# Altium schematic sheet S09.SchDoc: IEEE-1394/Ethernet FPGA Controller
size 381 x 254 mm; Revision: 3.2; SheetNumber: 9; SheetTotal: 10
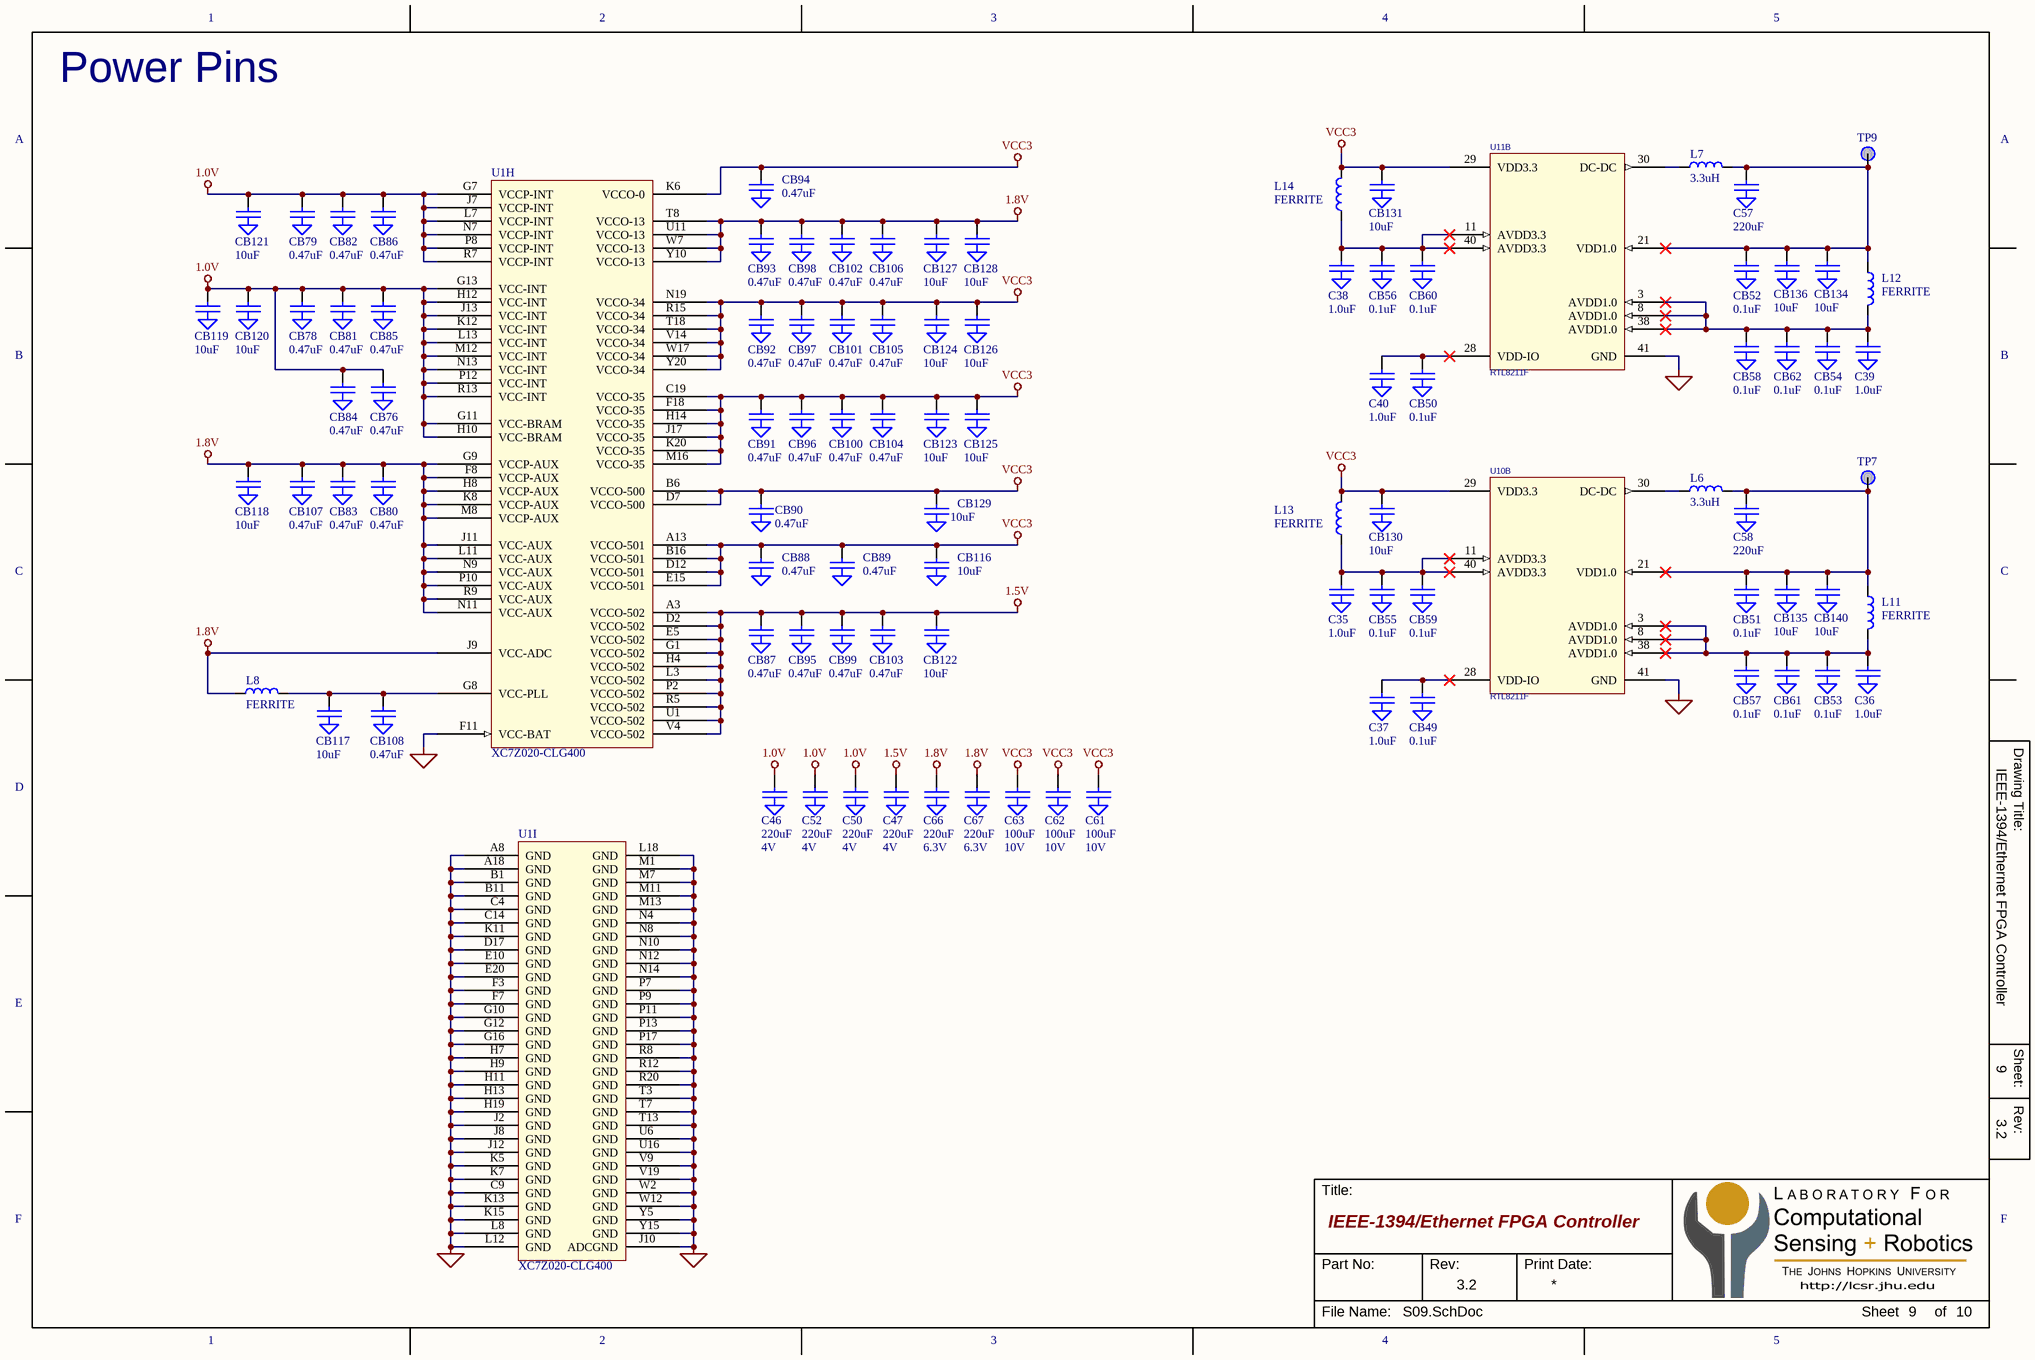
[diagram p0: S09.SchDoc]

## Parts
C35  1.0uF  [C0402]
C36  1.0uF  [C0402]
C37  1.0uF  [C0402]
C38  1.0uF  [C0402]
C39  1.0uF  [C0402]
C40  1.0uF  [C0402]
C46  220uF  Parameter 1: 4V  [C1206]
C47  220uF  Parameter 1: 4V  [C1206]
C50  220uF  Parameter 1: 4V  [C1206]
C52  220uF  Parameter 1: 4V  [C1206]
C57  220uF  [C1206]
C58  220uF  [C1206]
C61  100uF  Parameter 1: 10V  [C1210]
C62  100uF  Parameter 1: 10V  [C1210]
C63  100uF  Parameter 1: 10V  [C1210]
C66  220uF  Parameter 1: 6.3V  [C1210]
C67  220uF  Parameter 1: 6.3V  [C1210]
CB49  0.1uF  [C0201]
CB50  0.1uF  [C0201]
CB51  0.1uF  [C0201]
CB52  0.1uF  [C0201]
CB53  0.1uF  [C0201]
CB54  0.1uF  [C0201]
CB55  0.1uF  [C0201]
CB56  0.1uF  [C0201]
CB57  0.1uF  [C0201]
CB58  0.1uF  [C0201]
CB59  0.1uF  [C0201]
CB60  0.1uF  [C0201]
CB61  0.1uF  [C0201]
CB62  0.1uF  [C0201]
CB76  0.47uF  [CB0402]
CB78  0.47uF  [CB0402]
CB79  0.47uF  [CB0402]
CB80  0.47uF  [CB0402]
CB81  0.47uF  [CB0402]
CB82  0.47uF  [CB0402]
CB83  0.47uF  [CB0402]
CB84  0.47uF  [CB0402]
CB85  0.47uF  [CB0402]
CB86  0.47uF  [CB0402]
CB87  0.47uF  [CB0402]
CB88  0.47uF  [CB0402]
CB89  0.47uF  [CB0402]
CB90  0.47uF  [CB0402]
CB91  0.47uF  [CB0402]
CB92  0.47uF  [CB0402]
CB93  0.47uF  [CB0402]
CB94  0.47uF  [CB0402]
CB95  0.47uF  [CB0402]
CB96  0.47uF  [CB0402]
CB97  0.47uF  [CB0402]
CB98  0.47uF  [CB0402]
CB99  0.47uF  [CB0402]
CB100  0.47uF  [CB0402]
CB101  0.47uF  [CB0402]
CB102  0.47uF  [CB0402]
CB103  0.47uF  [CB0402]
CB104  0.47uF  [CB0402]
CB105  0.47uF  [CB0402]
CB106  0.47uF  [CB0402]
CB107  0.47uF  [CB0402]
CB108  0.47uF  [CB0402]
CB116  10uF  [CB0603]
CB117  10uF  [CB0603]
CB118  10uF  [CB0603]
CB119  10uF  [CB0603]
CB120  10uF  [CB0603]
CB121  10uF  [CB0603]
CB122  10uF  [CB0603]
CB123  10uF  [CB0603]
CB124  10uF  [CB0603]
CB125  10uF  [CB0603]
CB126  10uF  [CB0603]
CB127  10uF  [CB0603]
CB128  10uF  [CB0603]
CB129  10uF  [CB0603]
CB130  10uF  [CB0603]
CB131  10uF  [CB0603]
CB134  10uF  [CB0603]
CB135  10uF  [CB0603]
CB136  10uF  [CB0603]
CB140  10uF  [CB0603]
L6  3.3uH  [INDUCTOR-EPL2014]
L7  3.3uH  [INDUCTOR-EPL2014]
L8  FERRITE  [L0603]
L11  FERRITE  [l0402]
L12  FERRITE  [l0402]
L13  FERRITE  [l0402]
L14  FERRITE  [l0402]
TP7  PAD  [PAD25-SM]  (value not drawn)  (no BOM)
TP9  PAD  [PAD25-SM]  (value not drawn)  (no BOM)
U1  XC7Z020-CLG400  [BGA-400-08mm]  (parts H,I of 9)
U10  RTL8211F  [QFN-40-5MM]  (part B of 2)
U11  RTL8211F  [QFN-40-5MM]  (part B of 2)

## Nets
1.0V: C46.1 C50.1 C52.1 CB76.1 CB78.1 CB79.1 CB81.1 CB82.1 CB84.1 CB85.1 CB86.1 CB119.1 CB120.1 CB121.1 U1.G7(VCCP-INT) U1.G11(VCC-BRAM) U1.G13(VCC-INT) U1.H10(VCC-BRAM) U1.H12(VCC-INT) U1.J7(VCCP-INT) U1.J13(VCC-INT) U1.K12(VCC-INT) U1.L7(VCCP-INT) U1.L13(VCC-INT) U1.M12(VCC-INT) U1.N7(VCCP-INT) U1.N13(VCC-INT) U1.P8(VCCP-INT) U1.P12(VCC-INT) U1.R7(VCCP-INT) U1.R13(VCC-INT)
1.5V: C47.1 CB87.1 CB95.1 CB99.1 CB103.1 CB122.1 U1.A3(VCCO-502) U1.D2(VCCO-502) U1.E5(VCCO-502) U1.G1(VCCO-502) U1.H4(VCCO-502) U1.L3(VCCO-502) U1.P2(VCCO-502) U1.R5(VCCO-502) U1.U1(VCCO-502) U1.V4(VCCO-502)
1.8V: C66.1 C67.1 CB80.1 CB83.1 CB93.1 CB98.1 CB102.1 CB106.1 CB107.1 CB118.1 CB127.1 CB128.1 L8.1 U1.F8(VCCP-AUX) U1.G9(VCCP-AUX) U1.H8(VCCP-AUX) U1.J9(VCC-ADC) U1.J11(VCC-AUX) U1.K8(VCCP-AUX) U1.L11(VCC-AUX) U1.M8(VCCP-AUX) U1.N9(VCC-AUX) U1.N11(VCC-AUX) U1.P10(VCC-AUX) U1.R9(VCC-AUX) U1.T8(VCCO-13) U1.U11(VCCO-13) U1.W7(VCCO-13) U1.Y10(VCCO-13)
GND: C35.2(GND) C36.2(GND) C37.2(GND) C38.2(GND) C39.2(GND) C40.2(GND) C46.2(GND) C47.2(GND) C50.2(GND) C52.2(GND) C57.2(GND) C58.2(GND) C61.2(GND) C62.2(GND) C63.2(GND) C66.2(GND) C67.2(GND) CB49.2(GND) CB50.2(GND) CB51.2(GND) CB52.2(GND) CB53.2(GND) CB54.2(GND) CB55.2(GND) CB56.2(GND) CB57.2(GND) CB58.2(GND) CB59.2(GND) CB60.2(GND) CB61.2(GND) CB62.2(GND) CB76.2(GND) CB78.2(GND) CB79.2(GND) CB80.2(GND) CB81.2(GND) CB82.2(GND) CB83.2(GND) CB84.2(GND) CB85.2(GND) CB86.2(GND) CB87.2(GND) CB88.2(GND) CB89.2(GND) CB90.2(GND) CB91.2(GND) CB92.2(GND) CB93.2(GND) CB94.2(GND) CB95.2(GND) CB96.2(GND) CB97.2(GND) CB98.2(GND) CB99.2(GND) CB100.2(GND) CB101.2(GND) CB102.2(GND) CB103.2(GND) CB104.2(GND) CB105.2(GND) CB106.2(GND) CB107.2(GND) CB108.2(GND) CB116.2(GND) CB117.2(GND) CB118.2(GND) CB119.2(GND) CB120.2(GND) CB121.2(GND) CB122.2(GND) CB123.2(GND) CB124.2(GND) CB125.2(GND) CB126.2(GND) CB127.2(GND) CB128.2(GND) CB129.2(GND) CB130.2(GND) CB131.2(GND) CB134.2(GND) CB135.2(GND) CB136.2(GND) CB140.2(GND) U1.A8(GND) U1.A18(GND) U1.B1(GND) U1.B11(GND) U1.C4(GND) U1.C9(GND) U1.C14(GND) U1.D17(GND) U1.E10(GND) U1.E20(GND) U1.F3(GND) U1.F7(GND) U1.F11(VCC-BAT) U1.G10(GND) U1.G12(GND) U1.G16(GND) U1.H7(GND) U1.H9(GND) U1.H11(GND) U1.H13(GND) U1.H19(GND) U1.J2(GND) U1.J8(GND) U1.J10(ADCGND) U1.J12(GND) U1.K5(GND) U1.K7(GND) U1.K11(GND) U1.K13(GND) U1.K15(GND) U1.L8(GND) U1.L12(GND) U1.L18(GND) U1.M1(GND) U1.M7(GND) U1.M11(GND) U1.M13(GND) U1.N4(GND) U1.N8(GND) U1.N10(GND) U1.N12(GND) U1.N14(GND) U1.P7(GND) U1.P9(GND) U1.P11(GND) U1.P13(GND) U1.P17(GND) U1.R8(GND) U1.R12(GND) U1.R20(GND) U1.T3(GND) U1.T7(GND) U1.T13(GND) U1.U6(GND) U1.U16(GND) U1.V9(GND) U1.V19(GND) U1.W2(GND) U1.W12(GND) U1.Y5(GND) U1.Y15(GND) U10.41(GND) U11.41(GND)
VCC3: C61.1 C62.1 C63.1 CB88.1 CB89.1 CB90.1 CB91.1 CB92.1 CB94.1 CB96.1 CB97.1 CB100.1 CB101.1 CB104.1 CB105.1 CB116.1 CB123.1 CB124.1 CB125.1 CB126.1 CB129.1 CB130.1 CB131.1 L13.2 L14.2 U1.A13(VCCO-501) U1.B6(VCCO-500) U1.B16(VCCO-501) U1.C19(VCCO-35) U1.D7(VCCO-500) U1.D12(VCCO-501) U1.E15(VCCO-501) U1.F18(VCCO-35) U1.H14(VCCO-35) U1.J17(VCCO-35) U1.K6(VCCO-0) U1.K20(VCCO-35) U1.M16(VCCO-35) U1.N19(VCCO-34) U1.R15(VCCO-34) U1.T18(VCCO-34) U1.V14(VCCO-34) U1.W17(VCCO-34) U1.Y20(VCCO-34) U10.29(VDD3.3) U11.29(VDD3.3)
NetC35_1: C35.1 CB55.1 CB59.1 L13.1 U10.11(AVDD3.3) U10.40(AVDD3.3)
NetC36_1: C36.1 CB53.1 CB57.1 CB61.1 L11.2 U10.3(AVDD1.0) U10.8(AVDD1.0) U10.38(AVDD1.0)
NetC37_1: C37.1 CB49.1 U10.28(VDD-IO)
NetC38_1: C38.1 CB56.1 CB60.1 L14.1 U11.11(AVDD3.3) U11.40(AVDD3.3)
NetC39_1: C39.1 CB54.1 CB58.1 CB62.1 L12.2 U11.3(AVDD1.0) U11.8(AVDD1.0) U11.38(AVDD1.0)
NetC40_1: C40.1 CB50.1 U11.28(VDD-IO)
NetC57_1: C57.1 CB52.1 CB134.1 CB136.1 L7.2 L12.1 TP9.1 U11.21(VDD1.0)
NetC58_1: C58.1 CB51.1 CB135.1 CB140.1 L6.2 L11.1 TP7.1 U10.21(VDD1.0)
NetCB108_1: CB108.1 CB117.1 L8.2 U1.G8(VCC-PLL)
NetL6_1: L6.1 U10.30(DC-DC)
NetL7_1: L7.1 U11.30(DC-DC)

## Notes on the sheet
- Power Pins

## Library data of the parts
C35-C40 C46 C47 C50 C52 C57 C58 C61-C63 C66 C67 CB49-CB62 CB76 CB78-CB108 CB116-CB131 CB134-CB136 CB140 = CAP-GND
L6-L8 L11-L14 = INDUCTOR
U10 U11 = RTL8211F: Ethernet PHY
